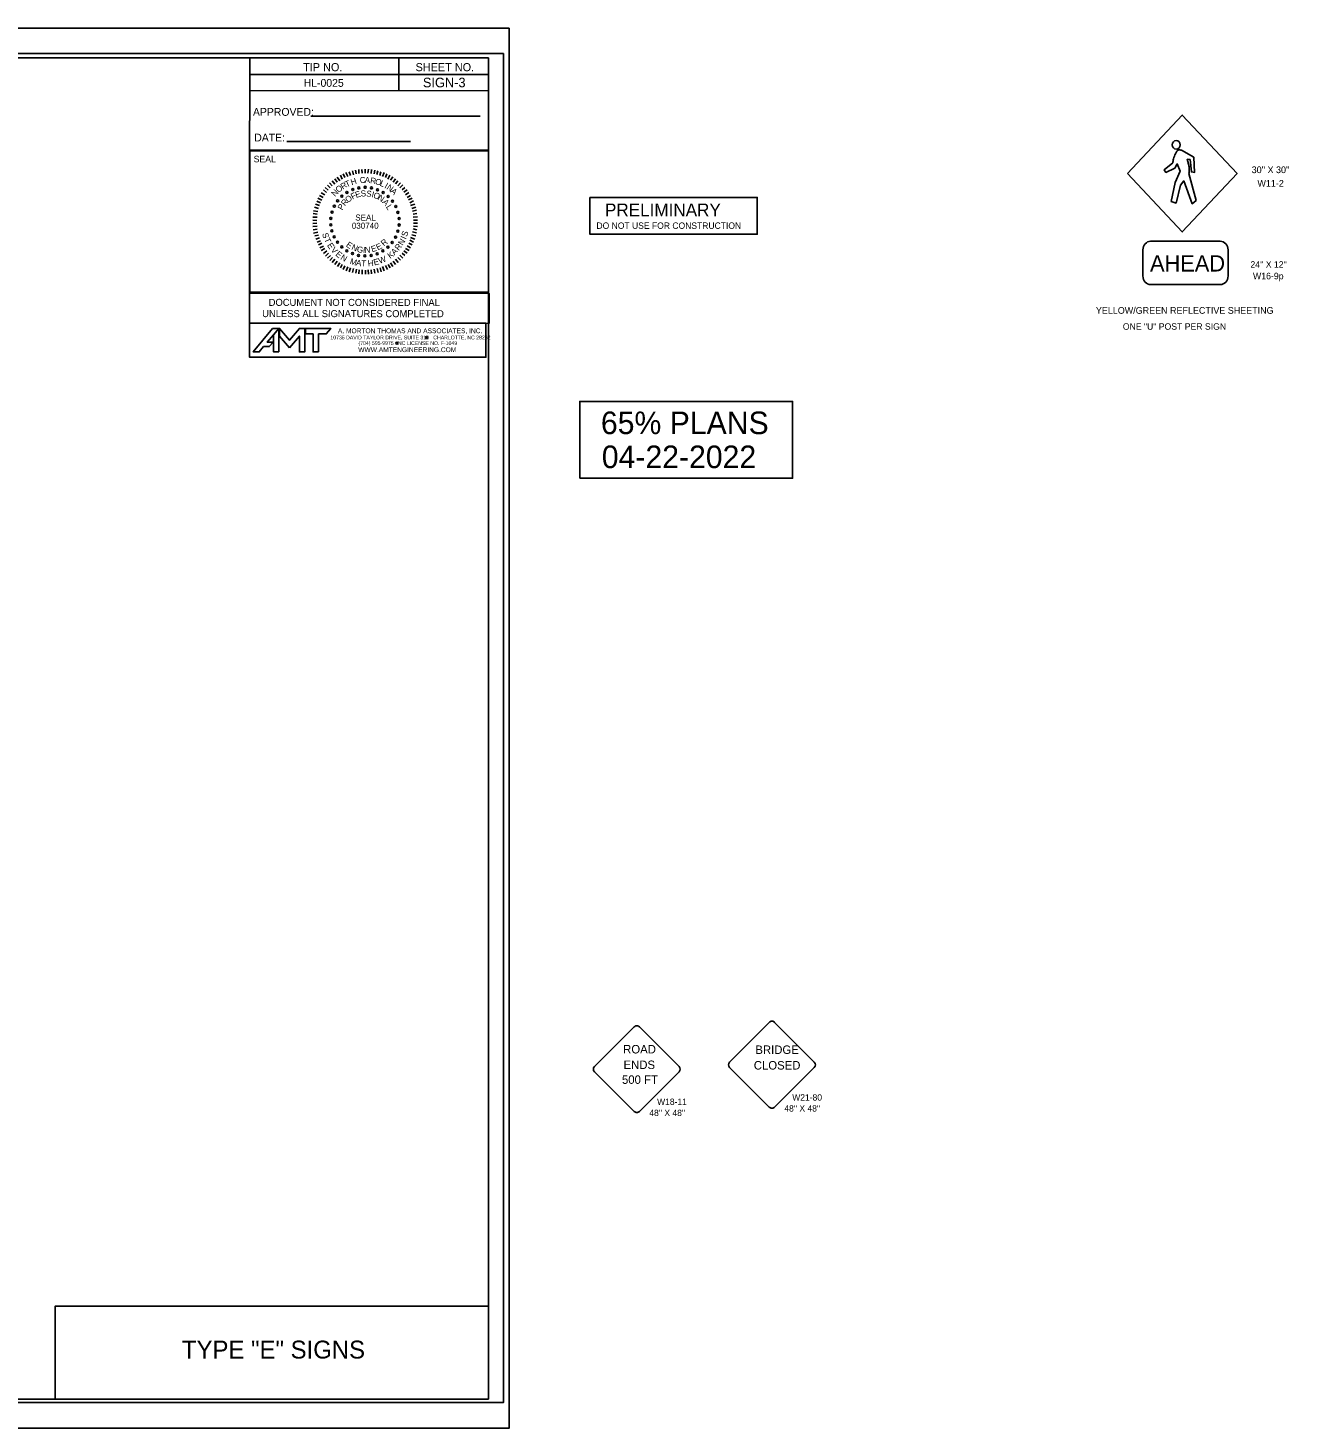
# Model space of a CAD drawing. Extents: x 2088420 to 2091362, y 751309 to 752707.
# Drawn here: x 2090375 to 2091362, y 751309 to 752405 of the extents above; entities that cross this region are included whole.
import ezdxf

# ---------------------------------------------------------------- set-up
doc = ezdxf.new("R2010")
doc.units = 0
for name, color, linetype in [('Default', 7, 'Continuous'), ('DEV PRELIMINARY STAMP CELL', 7, 'Continuous'), ('Gray Area Fill Shapes', 7, 'Continuous'), ('Old_Level_10', 7, 'Continuous'), ('Old_Level_9', 7, 'Continuous'), ('Prop Grid Mask', 7, 'Continuous'), ('Prop Sign E', 7, 'Continuous'), ('Prop Text', 7, 'Continuous'), ('Sheet Block Title CELL', 7, 'Continuous'), ('Sheet Plan CELL', 7, 'Continuous'), ('Sheet Plot Border Inside CELL', 7, 'Continuous'), ('Sheet Plot Border Outside CELL', 7, 'Continuous'), ('Sheet Sticker Exception Certification CELL', 7, 'Continuous'), ('Sheet Sticker Incomplete CELL', 7, 'Continuous'), ('Sheet Title CELL', 7, 'Continuous')]:
    doc.layers.add(name, color=color, linetype=linetype)

msp = doc.modelspace()

# ---------------------------------------------------------------- linework, layer by layer
at = {"layer": 'Default'}
for p, q in [((2090665, 752355.6), (2090665, 752380.6)), ((2090735.3, 752380.5), (2090735.3, 752380.5)), ((2090735.3, 752380.5), (2090735.3, 752380.5)), ((2090735.3, 752380.5), (2090735.3, 752380.5)), ((2090735.3, 752380.5), (2090735.3, 752380.5)), ((2090735.3, 752380.5), (2090735.3, 752380.5)), ((2090735.3, 752380.5), (2090735.3, 752380.5)), ((2090735.3, 752380.5), (2090735.3, 752380.5)), ((2090735.3, 752380.5), (2090735.3, 752380.5)), ((2090577.3, 752315.8), (2090674, 752315.8)), ((2091247.5, 752231), (2091247.5, 752210.6)), ((2091308.1, 752237.8), (2091253.6, 752237.8)), ((2091314.2, 752210.6), (2091314.2, 752231)), ((2091253.6, 752203.8), (2091308.1, 752203.8))]:
    msp.add_line(p, q, dxfattribs=at)
for points in [[(2091235.4, 752290.8), (2091278.3, 752336.5), (2091321.2, 752290.8), (2091278.3, 752245.1)], [(2090548.3, 752309.2), (2090735.3, 752309.2), (2090735.3, 752197.8), (2090548.3, 752197.8)]]:
    msp.add_lwpolyline(points, close=True, dxfattribs=at)
msp.add_ellipse((2091273.6, 752313.3), major_axis=(0, 3.31), ratio=0.938675, dxfattribs=at)
for centre, start_param, end_param in [((2091253.6, 752231), 3.141593, 4.712389), ((2091308.1, 752231), 1.570796, 3.141593), ((2091253.6, 752210.6), 4.712389, 6.283185), ((2091308.1, 752210.6), 0, 1.570796)]:
    msp.add_ellipse(centre, major_axis=(0, -6.8), ratio=0.891297, start_param=start_param, end_param=end_param, dxfattribs=at)
at = {"layer": 'DEV PRELIMINARY STAMP CELL'}
msp.add_lwpolyline([(2090814.6, 752272.1), (2090945.6, 752272.1), (2090945.6, 752243.2), (2090814.6, 752243.2)], close=True, dxfattribs=at)
msp.add_lwpolyline([(2090814.6, 752272.1), (2090945.6, 752272.1), (2090945.6, 752243.2), (2090814.6, 752243.2)], close=True, dxfattribs=at)
at = {"layer": 'Gray Area Fill Shapes'}
msp.add_lwpolyline([(2090814.6, 752272.1), (2090945.6, 752272.1), (2090945.6, 752243.2), (2090814.6, 752243.2)], close=True, dxfattribs=at)
at = {"layer": 'Old_Level_10'}
for points in [[(2091282.1, 752302), (2091284.4, 752301.7), (2091285.5, 752292), (2091288, 752291.6), (2091287.5, 752303.6), (2091277.8, 752309), (2091277.8, 752309)], [(2091270.9, 752299.1), (2091264.3, 752293.7), (2091265.5, 752291.6), (2091272.5, 752294.9), (2091274.4, 752298.3), (2091276.6, 752292.7), (2091272.7, 752283.7), (2091269.7, 752268.9), (2091273.5, 752267.7), (2091276.9, 752281.8), (2091279.5, 752285), (2091286.2, 752267.1), (2091289.2, 752269.7), (2091283.5, 752290.7)]]:
    msp.add_lwpolyline(points, dxfattribs=at)
for points in [[(2091277.8, 752309), (2091276.5, 752309.3), (2091275.2, 752309.1), (2091274.1, 752308.2), (2091273, 752306.3), (2091272.2, 752304.3), (2091271.5, 752302.3), (2091271.1, 752300.6), (2091270.9, 752299.1)], [(2091283.5, 752290.7), (2091283.8, 752292.5), (2091283.8, 752294.8), (2091283.4, 752297.4), (2091282.7, 752300.1), (2091282.1, 752302)]]:
    msp.add_spline(points, degree=3, dxfattribs=at)
at = {"layer": 'Old_Level_9'}
for p, q in [((2090612.8, 752285.1), (2090614.8, 752282.5)), ((2090614.8, 752286.6), (2090616.7, 752284.1)), ((2090616.8, 752288), (2090618.7, 752285.2)), ((2090619.2, 752289.5), (2090620.7, 752286.5)), ((2090621.5, 752290.5), (2090622.6, 752287.6)), ((2090623.6, 752291.5), (2090625.1, 752288.5)), ((2090626.2, 752292.2), (2090627.1, 752289.2)), ((2090628.6, 752293), (2090629.5, 752289.9)), ((2090631, 752293.5), (2090631.6, 752290.5)), ((2090633.6, 752293.9), (2090633.8, 752290.9)), ((2090636, 752294), (2090636.3, 752291)), ((2090638.6, 752294.2), (2090638.6, 752291)), ((2090641.2, 752294.2), (2090640.8, 752291)), ((2090643.6, 752293.9), (2090643.3, 752290.9)), ((2090646.2, 752293.5), (2090645.6, 752290.5)), ((2090648.6, 752293), (2090647.7, 752290)), ((2090651, 752292.2), (2090650.1, 752289.2)), ((2090653.6, 752291.5), (2090652.1, 752288.5)), ((2090655.7, 752290.5), (2090654.6, 752287.6)), ((2090658, 752289.5), (2090656.5, 752286.5)), ((2090660.3, 752288.2), (2090658.5, 752285.5)), ((2090662.3, 752286.6), (2090660.5, 752284.1)), ((2090664.3, 752285.1), (2090662.3, 752282.6)), ((2090603, 752273.7), (2090605.7, 752272.1)), ((2090604.3, 752275.7), (2090607.1, 752274.1)), ((2090606, 752277.9), (2090608.3, 752275.9)), ((2090607.3, 752279.9), (2090609.7, 752277.7)), ((2090609.1, 752281.6), (2090611.3, 752279.5)), ((2090610.8, 752283.5), (2090612.8, 752281.1)), ((2090666.3, 752283.5), (2090664.3, 752281.2)), ((2090668.1, 752281.9), (2090665.8, 752279.5)), ((2090669.8, 752279.9), (2090667.5, 752277.9)), ((2090671.5, 752277.9), (2090668.8, 752276.1)), ((2090672.8, 752275.9), (2090670.2, 752274.1)), ((2090674.2, 752273.7), (2090671.5, 752272.1)), ((2090599, 752264.4), (2090602.1, 752263.5)), ((2090599.7, 752266.7), (2090603, 752265.7)), ((2090600.7, 752269.1), (2090603.7, 752267.9)), ((2090601.7, 752271.4), (2090604.7, 752269.9)), ((2090675.5, 752271.5), (2090672.5, 752270.1)), ((2090676.5, 752269.4), (2090673.7, 752267.9)), ((2090677.5, 752266.7), (2090674.2, 752265.7)), ((2090678.2, 752264.4), (2090675.1, 752263.5)), ((2090597.6, 752254.4), (2090600.7, 752254.1)), ((2090597.6, 752251.7), (2090600.7, 752252)), ((2090597.7, 752256.7), (2090601, 752256.6)), ((2090598, 752259.4), (2090601.1, 752259)), ((2090598.3, 752261.7), (2090601.5, 752261.1)), ((2090678.8, 752262), (2090675.7, 752261.4)), ((2090679.2, 752259.6), (2090676.2, 752259)), ((2090679.5, 752257), (2090676.2, 752256.6)), ((2090679.6, 752254.4), (2090676.5, 752254.4)), ((2090679.6, 752252), (2090676.5, 752252)), ((2090597.7, 752249.2), (2090601, 752249.6)), ((2090598, 752246.7), (2090601.1, 752247.2)), ((2090598.3, 752244.2), (2090601.5, 752245)), ((2090599.1, 752241.9), (2090602.1, 752242.6)), ((2090600, 752239.5), (2090603, 752240.4)), ((2090677.5, 752239.5), (2090674.2, 752240.6)), ((2090678.2, 752242), (2090675.1, 752242.9)), ((2090678.8, 752244.4), (2090675.7, 752245.2)), ((2090679.2, 752246.7), (2090676.2, 752247.4)), ((2090679.5, 752249.4), (2090676.5, 752249.6)), ((2090601, 752237), (2090603.7, 752238.2)), ((2090602, 752234.9), (2090604.7, 752236.2)), ((2090603.1, 752232.5), (2090606, 752234)), ((2090604.3, 752230.5), (2090607.1, 752232.1)), ((2090606, 752228.2), (2090608.5, 752230.2)), ((2090671.5, 752228.5), (2090668.8, 752230.2)), ((2090673.1, 752230.5), (2090670.2, 752232.2)), ((2090674.2, 752232.5), (2090671.5, 752234.2)), ((2090675.5, 752234.9), (2090672.7, 752236.2)), ((2090676.5, 752237), (2090673.7, 752238.5)), ((2090607.5, 752226.2), (2090609.8, 752228.5)), ((2090609.1, 752224.5), (2090611.5, 752226.6)), ((2090611.1, 752222.7), (2090613.1, 752225.1)), ((2090612.8, 752221.1), (2090614.8, 752223.7)), ((2090614.8, 752219.5), (2090616.7, 752222.1)), ((2090617.1, 752218.1), (2090618.7, 752220.9)), ((2090619.2, 752216.9), (2090620.7, 752219.7)), ((2090621.5, 752215.7), (2090622.8, 752218.5)), ((2090656, 752215.7), (2090654.6, 752218.7)), ((2090658.1, 752216.9), (2090656.7, 752219.7)), ((2090660.3, 752218.1), (2090658.5, 752220.9)), ((2090662.3, 752219.7), (2090660.5, 752222.2)), ((2090664.5, 752221.1), (2090662.3, 752223.7)), ((2090666.3, 752222.9), (2090664.3, 752225.1)), ((2090668.1, 752224.5), (2090665.8, 752226.9)), ((2090669.8, 752226.5), (2090667.5, 752228.5)), ((2090623.8, 752214.7), (2090625.1, 752217.7)), ((2090626.2, 752213.9), (2090627.2, 752216.9)), ((2090628.8, 752213.4), (2090629.5, 752216.4)), ((2090631.2, 752212.7), (2090631.8, 752215.9)), ((2090633.6, 752212.4), (2090634, 752215.4)), ((2090636.2, 752212.1), (2090636.3, 752215.4)), ((2090638.8, 752212), (2090638.8, 752215.1)), ((2090641.2, 752212.1), (2090641, 752215.4)), ((2090643.7, 752212.4), (2090643.3, 752215.4)), ((2090646.3, 752212.7), (2090645.7, 752215.9)), ((2090648.7, 752213.4), (2090648, 752216.4)), ((2090651.1, 752213.9), (2090650.3, 752216.9)), ((2090653.6, 752214.7), (2090652.3, 752217.9))]:
    msp.add_line(p, q, dxfattribs=at)
for centre in [(2090620.4, 752273), (2090624.4, 752276), (2090628.9, 752278.2), (2090633.6, 752279.5), (2090638.6, 752280), (2090643.5, 752279.5), (2090648.3, 752278.1), (2090652.7, 752275.9), (2090656.6, 752272.9), (2090614.5, 752265.2), (2090617.1, 752269.4), (2090660, 752269.2), (2090662.6, 752265), (2090611.7, 752255.7), (2090611.7, 752250.7), (2090612.7, 752260.6), (2090664.3, 752260.4), (2090665.2, 752255.5), (2090665.2, 752250.5), (2090612.6, 752245.9), (2090614.4, 752241.2), (2090662.5, 752241), (2090664.3, 752245.7), (2090617, 752237), (2090620.3, 752233.3), (2090624.2, 752230.3), (2090652.5, 752230.2), (2090656.5, 752233.2), (2090659.8, 752236.8), (2090628.7, 752228.1), (2090633.4, 752226.7), (2090638.4, 752226.3), (2090643.3, 752226.7), (2090648.1, 752228)]:
    msp.add_circle(centre, 0.788, dxfattribs=at)
at = {"layer": 'Prop Grid Mask'}
msp.add_lwpolyline([(2090548.2, 752173.6), (2090733.2, 752173.6), (2090733.2, 752147), (2090548.2, 752147)], close=True, dxfattribs=at)
at = {"layer": 'Prop Sign E'}
for p, q in [((2090884.4, 751587.6), (2090853.3, 751556.5)), ((2090990.2, 751591.1), (2090959.1, 751560))]:
    msp.add_line(p, q, dxfattribs=at)
for points in [[(2090818.1, 751591.7), (2090849.2, 751622.8)], [(2090853.3, 751622.8), (2090884.4, 751591.7)], [(2090923.9, 751595.2), (2090955, 751626.3)], [(2090959.1, 751626.3), (2090990.2, 751595.2)], [(2090849.2, 751556.5), (2090818.1, 751587.6)], [(2090955, 751560), (2090923.9, 751591.1)]]:
    msp.add_lwpolyline(points, dxfattribs=at)
for centre, radius, start, end in [((2090957.1, 751624.3), 2.91, 89.9935, 135), ((2090957.1, 751624.3), 2.91, 44.987, 89.9935), ((2090851.3, 751620.8), 2.91, 89.9935, 135), ((2090851.3, 751620.8), 2.91, 44.987, 89.9935), ((2090926, 751593.1), 2.9, 135, 225), ((2090988.2, 751593.1), 2.9, 315, 45), ((2090820.2, 751589.7), 2.9, 135, 225), ((2090882.4, 751589.7), 2.9, 315, 45), ((2090851.3, 751558.6), 2.91, 225, 270), ((2090851.3, 751558.6), 2.91, 270, 315), ((2090957.1, 751562), 2.91, 225, 270), ((2090957.1, 751562), 2.91, 270, 315)]:
    msp.add_arc(centre, radius, start, end, dxfattribs=at)
at = {"layer": 'Prop Text'}
msp.add_line((2090596, 752335.7), (2090728.6, 752335.6), dxfattribs=at)
at = {"layer": 'Sheet Block Title CELL'}
for p, q in [((2090548.3, 752355.7), (2090548.3, 752380.6)), ((2090665, 752355.6), (2090665, 752380.6)), ((2090548.3, 752368.4), (2090665, 752368.3)), ((2090665, 752368.3), (2090735.3, 752368.3)), ((2090548.2, 752308.5), (2090548.3, 752355.7)), ((2090548.3, 752355.7), (2090735.3, 752355.5))]:
    msp.add_line(p, q, dxfattribs=at)
for points in [[(2090735.1, 752381.4), (2089235.1, 752381.4), (2089235.1, 751331.4), (2090735.1, 751331.4)], [(2090548.2, 752308.5), (2090735.2, 752308.4), (2090735.2, 752197), (2090548.2, 752197.1)], [(2090548.2, 752173.6), (2090733.2, 752173.6), (2090733.2, 752147), (2090548.2, 752147)], [(2090396, 751331.4), (2090735.1, 751331.4), (2090735.1, 751404.2), (2090396, 751404.2)]]:
    msp.add_lwpolyline(points, close=True, dxfattribs=at)
for points in [[(2090566.9, 752164.5), (2090571.1, 752169.5), (2090566.2, 752169.5), (2090551, 752151.2), (2090555.7, 752151.2), (2090559.1, 752155.3), (2090563.5, 752155.3), (2090566.5, 752158.7), (2090562, 752158.7), (2090566.9, 752164.5)], [(2090571.1, 752151.2), (2090571.1, 752169.5), (2090566.9, 752164.5), (2090566.9, 752151.2), (2090571.1, 752151.2)], [(2090579.3, 752154.4), (2090587.1, 752163.6), (2090587.1, 752151.2), (2090591.3, 752151.2), (2090591.3, 752169.5), (2090587.1, 752169.5), (2090579.3, 752160.3), (2090571.6, 752169.5), (2090571.6, 752163.6), (2090579.3, 752154.4)], [(2090602.1, 752151.2), (2090602.1, 752165.3), (2090608.2, 752165.3), (2090611.7, 752169.5), (2090591.8, 752169.5), (2090591.8, 752165.3), (2090597.9, 752165.3), (2090597.9, 752151.2), (2090602.1, 752151.2)]]:
    msp.add_lwpolyline(points, dxfattribs=at)
for centre in [(2090663.4, 752158), (2090686.7, 752162.4)]:
    msp.add_circle(centre, 0.833, dxfattribs=at)
at = {"layer": 'Sheet Plan CELL'}
for p, q in [((2090751.5, 752404.7), (2090751.5, 752404.7)), ((2090747, 752384.7), (2090747, 752384.7))]:
    msp.add_line(p, q, dxfattribs=at)
at = {"layer": 'Sheet Plot Border Inside CELL'}
msp.add_lwpolyline([(2090747, 752384.7), (2089081.6, 752384.7), (2089081.6, 751328.8), (2090747, 751328.8)], close=True, dxfattribs=at)
at = {"layer": 'Sheet Plot Border Outside CELL'}
msp.add_lwpolyline([(2090751.5, 752404.7), (2089068.6, 752404.7), (2089068.6, 751308.8), (2090751.5, 751308.8)], close=True, dxfattribs=at)
at = {"layer": 'Sheet Sticker Exception Certification CELL'}
msp.add_lwpolyline([(2090548.2, 752197.1), (2090735.6, 752197), (2090735.6, 752173.5), (2090548.2, 752173.6)], close=True, dxfattribs=at)
at = {"layer": 'Sheet Sticker Incomplete CELL'}
msp.add_lwpolyline([(2090806.6, 752052.3), (2090806.6, 752112.4), (2090973.2, 752112.4), (2090973.2, 752052.3)], close=True, dxfattribs=at)
at = {"layer": 'Sheet Title CELL'}
msp.add_line((2090735.3, 752197.7), (2090548.3, 752197.8), dxfattribs=at)

# ---------------------------------------------------------------- texts
at = {"layer": 'Default'}
for s, height, p in [("30'' X 30''", 5.244, (2091332.7, 752291.1)), ('W11-2', 5.24, (2091337.2, 752280.5)), ('AHEAD', 12.75, (2091253.1, 752214.1)), ("24'' X 12''", 5.067, (2091331.7, 752217.1)), ('W16-9p', 5.12, (2091333.7, 752208)), ('YELLOW/GREEN REFLECTIVE SHEETING', 5.245, (2091210.7, 752181))]:
    msp.add_text(s, height=height, dxfattribs=at).set_placement(p)
at = {"layer": 'DEV PRELIMINARY STAMP CELL'}
for s, height, p in [(' PRELIMINARY', 10, (2090822.7, 752257.3)), ('DO NOT USE FOR CONSTRUCTION', 5, (2090819.7, 752247.5))]:
    msp.add_text(s, height=height, dxfattribs=at).set_placement(p)
at = {"layer": 'Old_Level_9'}
for s, height, rotation, p in [('T', 4.72, 25.4358, (2090624.2, 752279.9)), ('H', 4.72, 17.7433, (2090628.1, 752281.6)), ('C', 4.72, 4.9399, (2090634.6, 752283.2)), ('A', 4.72, 357.9749, (2090638.2, 752283.5)), ('R', 4.72, 350.0216, (2090642.3, 752283.2)), ('O', 4.72, 343.0868, (2090646, 752282.6)), ('L', 4.72, 335.7459, (2090649.7, 752281.5)), ('N', 4.72, 48.0667, (2090615.1, 752272.4)), ('O', 4.72, 39.9442, (2090617.8, 752275.5)), ('R', 4.72, 32.1754, (2090621.2, 752278.1)), ('O', 4.7, 38.2518, (2090625.2, 752267.7)), ('F', 4.7, 26.4, (2090628.8, 752270.4)), ('E', 4.7, 16.5889, (2090631.6, 752271.7)), ('S', 4.7, 4.468, (2090635.3, 752272.7)), ('S', 4.7, 353.0415, (2090639.3, 752272.9)), ('I', 4.7, 345.4821, (2090643.3, 752272.4)), ('O', 4.7, 337.8749, (2090644.6, 752272.1)), ('N', 4.7, 327.393, (2090648, 752270.7)), ('I', 4.72, 330.806, (2090653.3, 752279.7)), ('N', 4.72, 324.9038, (2090655, 752278.9)), ('A', 4.72, 317.0051, (2090658.1, 752276.5)), ('P', 4.7, 60.1236, (2090620.8, 752261.7)), ('R', 4.7, 49.7478, (2090622.8, 752265)), ('A', 4.7, 313.9438, (2090651.7, 752268.1)), ('L', 4.7, 301.5323, (2090654.7, 752264.7)), ('S', 4.72, 288.212, (2090604.8, 752243.6)), ('T', 4.72, 295.6244, (2090606.3, 752239.2)), ('I', 4.72, 66.0464, (2090670.4, 752238.9)), ('S', 4.72, 72.2579, (2090671.3, 752241)), ('E', 4.72, 303.8225, (2090608.6, 752234.6)), ('V', 4.72, 311.9298, (2090611.4, 752230.7)), ('E', 4.72, 320.2312, (2090615, 752226.9)), ('E', 4.7, 324.8692, (2090623.2, 752234)), ('N', 4.7, 336.0584, (2090627.5, 752231.5)), ('G', 4.7, 347.4812, (2090631.8, 752229.5)), ('I', 4.7, 355.6246, (2090636.8, 752228.6)), ('N', 4.7, 3.1278, (2090638.3, 752228.6)), ('E', 4.7, 15.8057, (2090644, 752229.2)), ('E', 4.7, 27.1568, (2090648.6, 752230.6)), ('R', 4.7, 40.3493, (2090653.3, 752233.6)), ('K', 4.72, 36.141, (2090658.2, 752223.9)), ('A', 4.72, 43.5217, (2090661.5, 752226.7)), ('R', 4.72, 51.1503, (2090664.9, 752230.1)), ('N', 4.72, 59.3726, (2090668, 752234.1)), ('N', 4.72, 328.329, (2090618.9, 752223.9)), ('M', 4.72, 342.337, (2090626.3, 752220.2)), ('A', 4.72, 350.1822, (2090631.2, 752218.9)), ('T', 4.72, 357.3866, (2090635.5, 752218.2)), ('H', 4.72, 6.0112, (2090640.9, 752218)), ('E', 4.72, 14.1648, (2090645.8, 752218.8)), ('W', 4.72, 22.0058, (2090650.1, 752220))]:
    msp.add_text(s, height=height, rotation=rotation, dxfattribs=at).set_placement(p)
for s, p in [('030740', (2090628.2, 752247.6)), ('SEAL', (2090630.9, 752254))]:
    msp.add_text(s, height=4.7, dxfattribs=at).set_placement(p)
at = {"layer": 'Prop Sign E'}
for s, height, p in [('ROAD', 6.64, (2090840.6, 751602)), ('BRIDGE', 6.64, (2090944.1, 751601.6)), ('ENDS', 6.64, (2090840.9, 751589.8)), ('CLOSED', 6.64, (2090942.9, 751589.4)), ('500 FT', 6.64, (2090839.7, 751578.2)), ('W18-11', 4.98, (2090867.2, 751561.7)), ("48'' X 48''", 4.98, (2090966.8, 751556.5)), ('W21-80', 4.98, (2090973, 751565.1)), ("48'' X 48''", 4.98, (2090861.1, 751553))]:
    msp.add_text(s, height=height, dxfattribs=at).set_placement(p)
at = {"layer": 'Prop Text'}
for s, height, p in [('TIP NO.', 6.36, (2090590.1, 752370.9)), ('SHEET NO.', 6.36, (2090678.1, 752370.9)), ('HL-0025', 6.11, (2090590.5, 752358.7)), ('APPROVED:', 6.11, (2090550.8, 752336)), ('DATE:', 6.11, (2090551.8, 752315.9)), ('SEAL', 5.09, (2090551.3, 752299.6))]:
    msp.add_text(s, height=height, rotation=359.9641, dxfattribs=at).set_placement(p)
msp.add_text('ONE "U" POST PER SIGN', height=5.067, dxfattribs=at).set_placement((2091231.8, 752168.5))
at = {"layer": 'Sheet Block Title CELL'}
for s, height, p in [('10735 DAVID TAYLOR DRIVE, SUITE 310   CHARLOTTE, NC 28262', 2.917, (2090611.4, 752161)), ('A. MORTON THOMAS AND ASSOCIATES, INC.', 3.75, (2090617.3, 752165.8)), ('WWW.AMTENGINEERING.COM', 3.75, (2090633.2, 752151)), ('(704) 595-9975   NC LICENSE NO. F-1049', 2.917, (2090633.4, 752156.6))]:
    msp.add_text(s, height=height, rotation=359.9995, dxfattribs=at).set_placement(p)
at = {"layer": 'Sheet Sticker Exception Certification CELL'}
for s, p in [('DOCUMENT NOT CONSIDERED FINAL', (2090563.1, 752187.2)), ('UNLESS ALL SIGNATURES COMPLETED', (2090558, 752178.4))]:
    msp.add_text(s, height=5.5, rotation=359.9692, dxfattribs=at).set_placement(p)
at = {"layer": 'Sheet Sticker Incomplete CELL'}
for s, p in [('65% PLANS', (2090823.2, 752086.8)), ('04-22-2022', (2090823.9, 752060.2))]:
    msp.add_text(s, height=17.67, rotation=360, dxfattribs=at).set_placement(p)
at = {"layer": 'Sheet Title CELL'}
for s, height, rotation, p in [('SIGN-3', 7.5, 359.9683, (2090683.8, 752358.3)), ('TYPE "E" SIGNS', 14, 359.9992, (2090495.2, 751363.2))]:
    msp.add_text(s, height=height, rotation=rotation, dxfattribs=at).set_placement(p)

doc.saveas('drawing.dxf')
